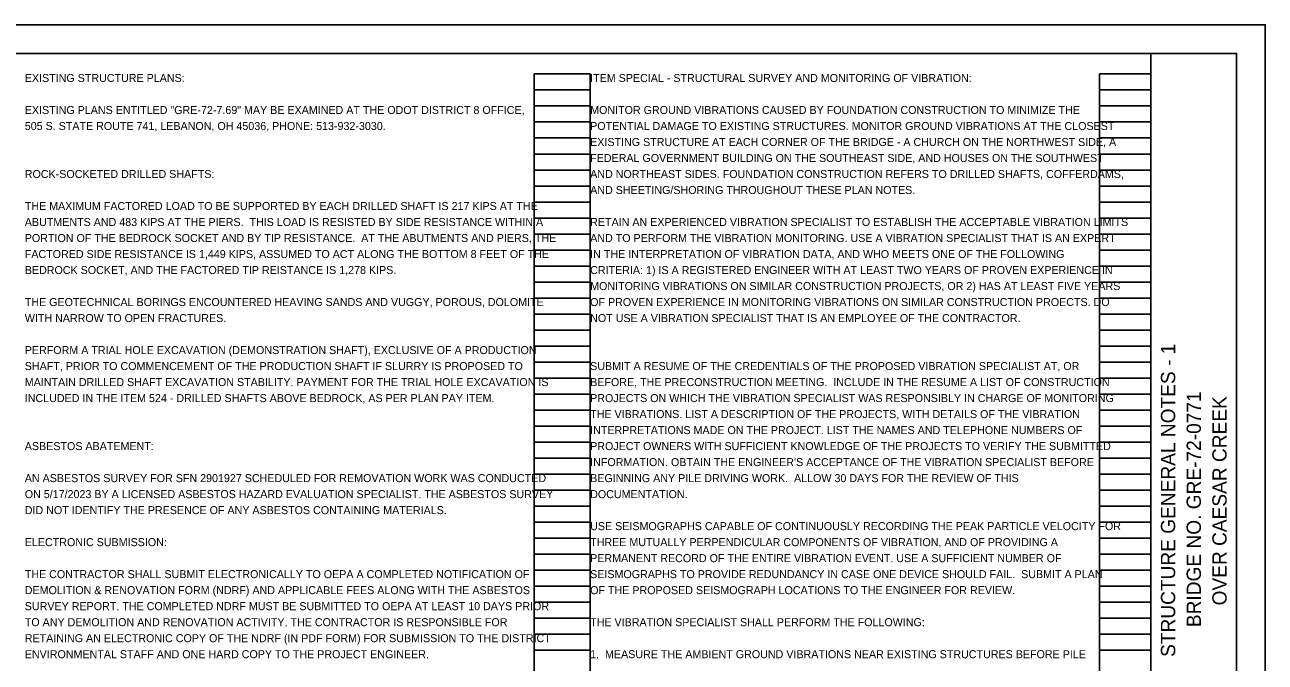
# Model space of a CAD drawing. Extents: x 0 to 34, y 0 to 22.
# Drawn here: x 12.29 to 34, y 10.85 to 22 of the extents above; entities that cross this region are included whole.
import ezdxf

# ---------------------------------------------------------------- set-up
doc = ezdxf.new("R2010")
doc.units = 0
for name, color, linetype in [('SH_Border', 7, 'Continuous'), ('SH_Cut_Line', 7, 'Continuous'), ('SH_Data', 7, 'Continuous'), ('SH_Text', 7, 'Continuous')]:
    doc.layers.add(name, color=color, linetype=linetype)

msp = doc.modelspace()

# ---------------------------------------------------------------- linework, layer by layer
at = {"layer": 'SH_Border'}
msp.add_line((32, 0.5), (32, 21.5), dxfattribs=at)
msp.add_lwpolyline([(1.5, 21.5), (33.5, 21.5), (33.5, 0.5), (1.5, 0.5)], close=True, dxfattribs=at)
at = {"layer": 'SH_Cut_Line'}
msp.add_lwpolyline([(0, 0), (34, 0), (34, 22), (0, 22)], close=True, dxfattribs=at)
at = {"layer": 'SH_Data'}
for p, q in [((21.207, 0.98), (21.207, 21.14)), ((21.207, 21.14), (22.187, 21.14)), ((22.187, 0.98), (22.187, 21.14)), ((31.1, 0.98), (31.1, 21.14)), ((31.1, 21.14), (32, 21.14)), ((32, 0.98), (32, 21.14)), ((21.207, 20.86), (22.187, 20.86)), ((31.1, 20.86), (32, 20.86)), ((21.207, 20.58), (22.187, 20.58)), ((31.1, 20.58), (32, 20.58)), ((21.207, 20.3), (22.187, 20.3)), ((31.1, 20.3), (32, 20.3)), ((21.207, 20.02), (22.187, 20.02)), ((31.1, 20.02), (32, 20.02)), ((21.207, 19.74), (22.187, 19.74)), ((31.1, 19.74), (32, 19.74)), ((21.207, 19.46), (22.187, 19.46)), ((31.1, 19.46), (32, 19.46)), ((21.207, 19.18), (22.187, 19.18)), ((31.1, 19.18), (32, 19.18)), ((21.207, 18.9), (22.187, 18.9)), ((31.1, 18.9), (32, 18.9)), ((21.207, 18.62), (22.187, 18.62)), ((31.1, 18.62), (32, 18.62)), ((21.207, 18.34), (22.187, 18.34)), ((31.1, 18.34), (32, 18.34)), ((21.207, 18.06), (22.187, 18.06)), ((31.1, 18.06), (32, 18.06)), ((21.207, 17.78), (22.187, 17.78)), ((31.1, 17.78), (32, 17.78)), ((21.207, 17.5), (22.187, 17.5)), ((31.1, 17.5), (32, 17.5)), ((21.207, 17.22), (22.187, 17.22)), ((31.1, 17.22), (32, 17.22)), ((21.207, 16.94), (22.187, 16.94)), ((31.1, 16.94), (32, 16.94)), ((21.207, 16.66), (22.187, 16.66)), ((31.1, 16.66), (32, 16.66)), ((21.207, 16.38), (22.187, 16.38)), ((31.1, 16.38), (32, 16.38)), ((21.207, 16.1), (22.187, 16.1)), ((31.1, 16.1), (32, 16.1)), ((21.207, 15.82), (22.187, 15.82)), ((31.1, 15.82), (32, 15.82)), ((21.207, 15.54), (22.187, 15.54)), ((31.1, 15.54), (32, 15.54)), ((21.207, 15.26), (22.187, 15.26)), ((31.1, 15.26), (32, 15.26)), ((21.207, 14.98), (22.187, 14.98)), ((31.1, 14.98), (32, 14.98)), ((21.207, 14.7), (22.187, 14.7)), ((31.1, 14.7), (32, 14.7)), ((21.207, 14.42), (22.187, 14.42)), ((31.1, 14.42), (32, 14.42)), ((21.207, 14.14), (22.187, 14.14)), ((31.1, 14.14), (32, 14.14)), ((21.207, 13.86), (22.187, 13.86)), ((31.1, 13.86), (32, 13.86)), ((21.207, 13.58), (22.187, 13.58)), ((31.1, 13.58), (32, 13.58)), ((21.207, 13.3), (22.187, 13.3)), ((31.1, 13.3), (32, 13.3)), ((21.207, 13.02), (22.187, 13.02)), ((31.1, 13.02), (32, 13.02)), ((21.207, 12.74), (22.187, 12.74)), ((31.1, 12.74), (32, 12.74)), ((21.207, 12.46), (22.187, 12.46)), ((31.1, 12.46), (32, 12.46)), ((21.207, 12.18), (22.187, 12.18)), ((31.1, 12.18), (32, 12.18)), ((21.207, 11.9), (22.187, 11.9)), ((31.1, 11.9), (32, 11.9)), ((21.207, 11.62), (22.187, 11.62)), ((31.1, 11.62), (32, 11.62)), ((21.207, 11.34), (22.187, 11.34)), ((31.1, 11.34), (32, 11.34)), ((21.207, 11.06), (22.187, 11.06)), ((31.1, 11.06), (32, 11.06))]:
    msp.add_line(p, q, dxfattribs=at)

# ---------------------------------------------------------------- texts
for s, p in [('STRUCTURE GENERAL NOTES - 1', (32.425, 10.942)), ('BRIDGE NO. GRE-72-0771', (32.875, 11.463)), ('OVER CAESAR CREEK', (33.325, 11.843))]:
    msp.add_text(s, height=0.25, rotation=90, dxfattribs=at).set_placement(p)
at = {"layer": 'SH_Text'}
for s, p in [('EXISTING STRUCTURE PLANS:', (12.293, 21)), ('ITEM SPECIAL - STRUCTURAL SURVEY AND MONITORING OF VIBRATION:', (22.187, 21)), ('EXISTING PLANS ENTITLED "GRE-72-7.69" MAY BE EXAMINED AT THE ODOT DISTRICT 8 OFFICE, ', (12.293, 20.44)), ('MONITOR GROUND VIBRATIONS CAUSED BY FOUNDATION CONSTRUCTION TO MINIMIZE THE ', (22.187, 20.44)), ('505 S. STATE ROUTE 741, LEBANON, OH 45036, PHONE: 513-932-3030.', (12.293, 20.16)), ('POTENTIAL DAMAGE TO EXISTING STRUCTURES. MONITOR GROUND VIBRATIONS AT THE CLOSEST ', (22.187, 20.16)), ('EXISTING STRUCTURE AT EACH CORNER OF THE BRIDGE - A CHURCH ON THE NORTHWEST SIDE, A ', (22.187, 19.88)), ('FEDERAL GOVERNMENT BUILDING ON THE SOUTHEAST SIDE, AND HOUSES ON THE SOUTHWEST ', (22.187, 19.6)), ('ROCK-SOCKETED DRILLED SHAFTS:', (12.293, 19.32)), ('AND NORTHEAST SIDES. FOUNDATION CONSTRUCTION REFERS TO DRILLED SHAFTS, COFFERDAMS, ', (22.187, 19.32)), ('AND SHEETING/SHORING THROUGHOUT THESE PLAN NOTES.', (22.187, 19.04)), ('THE MAXIMUM FACTORED LOAD TO BE SUPPORTED BY EACH DRILLED SHAFT IS 217 KIPS AT THE ', (12.293, 18.76)), ('ABUTMENTS AND 483 KIPS AT THE PIERS.  THIS LOAD IS RESISTED BY SIDE RESISTANCE WITHIN A ', (12.293, 18.48)), ('RETAIN AN EXPERIENCED VIBRATION SPECIALIST TO ESTABLISH THE ACCEPTABLE VIBRATION LIMITS ', (22.187, 18.48)), ('PORTION OF THE BEDROCK SOCKET AND BY TIP RESISTANCE.  AT THE ABUTMENTS AND PIERS, THE ', (12.293, 18.2)), ('AND TO PERFORM THE VIBRATION MONITORING. USE A VIBRATION SPECIALIST THAT IS AN EXPERT ', (22.187, 18.2)), ('FACTORED SIDE RESISTANCE IS 1,449 KIPS, ASSUMED TO ACT ALONG THE BOTTOM 8 FEET OF THE ', (12.293, 17.92)), ('IN THE INTERPRETATION OF VIBRATION DATA, AND WHO MEETS ONE OF THE FOLLOWING ', (22.187, 17.92)), ('BEDROCK SOCKET, AND THE FACTORED TIP REISTANCE IS 1,278 KIPS.', (12.293, 17.64)), ('CRITERIA: 1) IS A REGISTERED ENGINEER WITH AT LEAST TWO YEARS OF PROVEN EXPERIENCE IN ', (22.187, 17.64)), ('MONITORING VIBRATIONS ON SIMILAR CONSTRUCTION PROJECTS, OR 2) HAS AT LEAST FIVE YEARS ', (22.187, 17.36)), ('THE GEOTECHNICAL BORINGS ENCOUNTERED HEAVING SANDS AND VUGGY, POROUS, DOLOMITE ', (12.293, 17.08)), ('OF PROVEN EXPERIENCE IN MONITORING VIBRATIONS ON SIMILAR CONSTRUCTION PROECTS. DO ', (22.187, 17.08)), ('WITH NARROW TO OPEN FRACTURES.', (12.293, 16.8)), ('NOT USE A VIBRATION SPECIALIST THAT IS AN EMPLOYEE OF THE CONTRACTOR.', (22.187, 16.8)), ('PERFORM A TRIAL HOLE EXCAVATION (DEMONSTRATION SHAFT), EXCLUSIVE OF A PRODUCTION ', (12.293, 16.24)), ('SHAFT, PRIOR TO COMMENCEMENT OF THE PRODUCTION SHAFT IF SLURRY IS PROPOSED TO ', (12.293, 15.96)), ('SUBMIT A RESUME OF THE CREDENTIALS OF THE PROPOSED VIBRATION SPECIALIST AT, OR ', (22.187, 15.96)), ('MAINTAIN DRILLED SHAFT EXCAVATION STABILITY. PAYMENT FOR THE TRIAL HOLE EXCAVATION IS ', (12.293, 15.68)), ('BEFORE, THE PRECONSTRUCTION MEETING.  INCLUDE IN THE RESUME A LIST OF CONSTRUCTION ', (22.187, 15.68)), ('INCLUDED IN THE ITEM 524 - DRILLED SHAFTS ABOVE BEDROCK, AS PER PLAN PAY ITEM.', (12.293, 15.4)), ('PROJECTS ON WHICH THE VIBRATION SPECIALIST WAS RESPONSIBLY IN CHARGE OF MONITORING', (22.187, 15.4)), ('THE VIBRATIONS. LIST A DESCRIPTION OF THE PROJECTS, WITH DETAILS OF THE VIBRATION ', (22.187, 15.12)), ('INTERPRETATIONS MADE ON THE PROJECT. LIST THE NAMES AND TELEPHONE NUMBERS OF ', (22.187, 14.84)), ('ASBESTOS ABATEMENT:', (12.293, 14.56)), ('PROJECT OWNERS WITH SUFFICIENT KNOWLEDGE OF THE PROJECTS TO VERIFY THE SUBMITTED ', (22.187, 14.56)), ("INFORMATION. OBTAIN THE ENGINEER'S ACCEPTANCE OF THE VIBRATION SPECIALIST BEFORE ", (22.187, 14.28)), ('AN ASBESTOS SURVEY FOR SFN 2901927 SCHEDULED FOR REMOVATION WORK WAS CONDUCTED ', (12.293, 14)), ('BEGINNING ANY PILE DRIVING WORK.  ALLOW 30 DAYS FOR THE REVIEW OF THIS ', (22.187, 14)), ('ON 5/17/2023 BY A LICENSED ASBESTOS HAZARD EVALUATION SPECIALIST. THE ASBESTOS SURVEY ', (12.293, 13.72)), ('DOCUMENTATION.', (22.187, 13.72)), ('DID NOT IDENTIFY THE PRESENCE OF ANY ASBESTOS CONTAINING MATERIALS.', (12.293, 13.44)), ('USE SEISMOGRAPHS CAPABLE OF CONTINUOUSLY RECORDING THE PEAK PARTICLE VELOCITY FOR ', (22.187, 13.16)), ('ELECTRONIC SUBMISSION:', (12.293, 12.88)), ('THREE MUTUALLY PERPENDICULAR COMPONENTS OF VIBRATION, AND OF PROVIDING A ', (22.187, 12.88)), ('PERMANENT RECORD OF THE ENTIRE VIBRATION EVENT. USE A SUFFICIENT NUMBER OF ', (22.187, 12.6)), ('THE CONTRACTOR SHALL SUBMIT ELECTRONICALLY TO OEPA A COMPLETED NOTIFICATION OF ', (12.293, 12.32)), ('SEISMOGRAPHS TO PROVIDE REDUNDANCY IN CASE ONE DEVICE SHOULD FAIL.  SUBMIT A PLAN ', (22.187, 12.32)), ('DEMOLITION & RENOVATION FORM (NDRF) AND APPLICABLE FEES ALONG WITH THE ASBESTOS ', (12.293, 12.04)), ('OF THE PROPOSED SEISMOGRAPH LOCATIONS TO THE ENGINEER FOR REVIEW.', (22.187, 12.04)), ('SURVEY REPORT. THE COMPLETED NDRF MUST BE SUBMITTED TO OEPA AT LEAST 10 DAYS PRIOR ', (12.293, 11.76)), ('TO ANY DEMOLITION AND RENOVATION ACTIVITY. THE CONTRACTOR IS RESPONSIBLE FOR ', (12.293, 11.48)), ('THE VIBRATION SPECIALIST SHALL PERFORM THE FOLLOWING:', (22.187, 11.48)), ('RETAINING AN ELECTRONIC COPY OF THE NDRF (IN PDF FORM) FOR SUBMISSION TO THE DISTRICT ', (12.293, 11.2)), ('ENVIRONMENTAL STAFF AND ONE HARD COPY TO THE PROJECT ENGINEER.', (12.293, 10.92)), ('1.  MEASURE THE AMBIENT GROUND VIBRATIONS NEAR EXISTING STRUCTURES BEFORE PILE ', (22.187, 10.92))]:
    msp.add_text(s, height=0.14, dxfattribs=at).set_placement(p)

doc.saveas('drawing.dxf')
